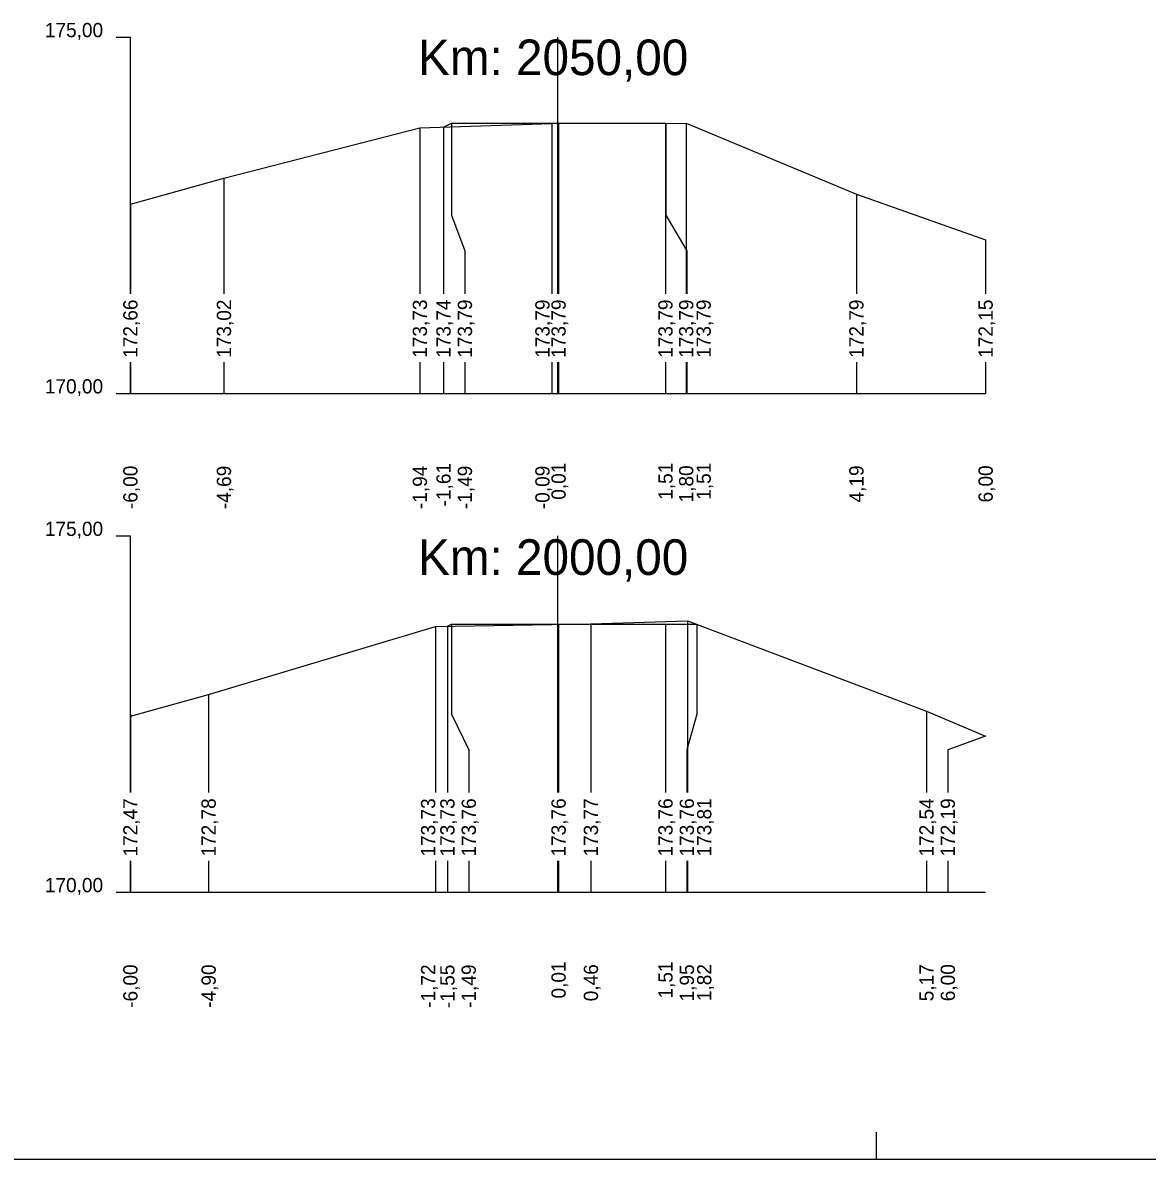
# Model space of a CAD drawing. Extents: x -614174 to -599765, y -1185887 to -1181080.
# Drawn here: x -600970.94 to -600955.16, y -1184449.09 to -1184433.14 of the extents above; entities that cross this region are included whole.
import ezdxf

# ---------------------------------------------------------------- set-up
doc = ezdxf.new("R2010")
doc.units = 0
for name, color, linetype in [('11', 7, 'Continuous'), ('16', 7, 'Continuous'), ('21', 7, 'Continuous'), ('28', 7, 'Continuous'), ('59', 7, 'Continuous'), ('8', 7, 'Continuous'), ('návrh', 7, 'Continuous')]:
    doc.layers.add(name, color=color, linetype=linetype)

msp = doc.modelspace()

# ---------------------------------------------------------------- linework, layer by layer
for points in [[(-600969.427, -1184435.687), (-600968.114, -1184435.322), (-600965.365, -1184434.616), (-600963.513, -1184434.554), (-600961.628, -1184434.549), (-600959.24, -1184435.547), (-600957.427, -1184436.188)], [(-600965.033, -1184434.605), (-600964.919, -1184434.548), (-600963.419, -1184434.548), (-600961.919, -1184434.548), (-600961.916, -1184434.55)], [(-600965.033, -1184434.605), (-600965.033, -1184434.605), (-600965.033, -1184434.605)], [(-600964.919, -1184434.548), (-600964.919, -1184434.548), (-600964.919, -1184434.548)], [(-600963.419, -1184434.548), (-600963.419, -1184434.548), (-600963.419, -1184434.548)], [(-600961.919, -1184434.548), (-600961.919, -1184434.548), (-600961.919, -1184434.548)], [(-600969.427, -1184442.871), (-600968.329, -1184442.565), (-600965.145, -1184441.613), (-600962.965, -1184441.576), (-600961.608, -1184441.531), (-600958.257, -1184442.802), (-600957.427, -1184443.151)], [(-600964.979, -1184441.61), (-600964.919, -1184441.58), (-600963.419, -1184441.58), (-600961.919, -1184441.58), (-600961.477, -1184441.58)], [(-600964.979, -1184441.61), (-600964.979, -1184441.61), (-600964.979, -1184441.61)], [(-600964.919, -1184441.58), (-600964.919, -1184441.58), (-600964.919, -1184441.58)], [(-600963.419, -1184441.58), (-600963.419, -1184441.58), (-600963.419, -1184441.58)], [(-600961.919, -1184441.58), (-600961.919, -1184441.58), (-600961.919, -1184441.58)]]:
    msp.add_lwpolyline(points)
at = {"layer": '11'}
for points in [[(-600965.365, -1184434.616), (-600965.365, -1184435.842), (-600965.365, -1184436.342), (-600965.365, -1184436.944)], [(-600965.033, -1184434.605), (-600965.033, -1184435.842), (-600965.033, -1184436.342), (-600965.033, -1184436.944)], [(-600964.919, -1184434.548), (-600964.919, -1184435.842), (-600964.733, -1184436.342), (-600964.733, -1184436.944)], [(-600963.513, -1184434.554), (-600963.513, -1184435.842), (-600963.513, -1184436.342), (-600963.513, -1184436.944)], [(-600963.419, -1184434.548), (-600963.419, -1184435.842), (-600963.419, -1184436.342), (-600963.419, -1184436.944)], [(-600961.919, -1184434.548), (-600961.919, -1184435.842), (-600961.919, -1184436.342), (-600961.919, -1184436.944)], [(-600961.916, -1184434.55), (-600961.916, -1184435.842), (-600961.619, -1184436.342), (-600961.619, -1184436.944)], [(-600961.628, -1184434.549), (-600961.628, -1184435.842), (-600961.628, -1184436.342), (-600961.628, -1184436.944)], [(-600968.114, -1184435.322), (-600968.114, -1184435.842), (-600968.114, -1184436.342), (-600968.114, -1184436.944)], [(-600959.24, -1184435.547), (-600959.24, -1184435.842), (-600959.24, -1184436.342), (-600959.24, -1184436.944)], [(-600969.427, -1184435.687), (-600969.427, -1184435.842), (-600969.427, -1184436.342), (-600969.427, -1184436.944)], [(-600957.427, -1184436.188), (-600957.427, -1184436.342), (-600957.427, -1184436.944)], [(-600969.427, -1184437.902), (-600969.427, -1184438.342)], [(-600968.114, -1184437.902), (-600968.114, -1184438.342)], [(-600965.365, -1184437.902), (-600965.365, -1184438.342)], [(-600965.033, -1184437.902), (-600965.033, -1184438.342)], [(-600964.733, -1184437.902), (-600964.733, -1184438.342)], [(-600963.513, -1184437.902), (-600963.513, -1184438.342)], [(-600963.419, -1184437.902), (-600963.419, -1184438.342)], [(-600961.919, -1184437.902), (-600961.919, -1184438.342)], [(-600961.628, -1184437.902), (-600961.628, -1184438.342)], [(-600961.619, -1184437.902), (-600961.619, -1184438.342)], [(-600959.24, -1184437.902), (-600959.24, -1184438.342)], [(-600957.427, -1184437.902), (-600957.427, -1184438.342)], [(-600961.608, -1184441.531), (-600961.608, -1184442.842), (-600961.608, -1184443.342), (-600961.608, -1184443.944)], [(-600965.145, -1184441.613), (-600965.145, -1184442.842), (-600965.145, -1184443.342), (-600965.145, -1184443.944)], [(-600964.979, -1184441.61), (-600964.979, -1184442.842), (-600964.979, -1184443.342), (-600964.979, -1184443.944)], [(-600964.919, -1184441.58), (-600964.919, -1184442.842), (-600964.679, -1184443.342), (-600964.679, -1184443.944)], [(-600963.419, -1184441.58), (-600963.419, -1184442.842), (-600963.419, -1184443.342), (-600963.419, -1184443.944)], [(-600962.965, -1184441.576), (-600962.965, -1184442.842), (-600962.965, -1184443.342), (-600962.965, -1184443.944)], [(-600961.919, -1184441.58), (-600961.919, -1184442.842), (-600961.919, -1184443.342), (-600961.919, -1184443.944)], [(-600961.477, -1184441.58), (-600961.477, -1184442.842), (-600961.619, -1184443.342), (-600961.619, -1184443.944)], [(-600968.329, -1184442.565), (-600968.329, -1184442.842), (-600968.329, -1184443.342), (-600968.329, -1184443.944)], [(-600958.257, -1184442.802), (-600958.257, -1184442.842), (-600958.257, -1184443.342), (-600958.257, -1184443.944)], [(-600969.427, -1184442.871), (-600969.427, -1184442.842), (-600969.427, -1184443.342), (-600969.427, -1184443.944)], [(-600957.427, -1184443.151), (-600957.957, -1184443.342), (-600957.957, -1184443.944)], [(-600969.427, -1184444.902), (-600969.427, -1184445.342)], [(-600968.329, -1184444.902), (-600968.329, -1184445.342)], [(-600965.145, -1184444.902), (-600965.145, -1184445.342)], [(-600964.979, -1184444.902), (-600964.979, -1184445.342)], [(-600964.679, -1184444.902), (-600964.679, -1184445.342)], [(-600963.419, -1184444.902), (-600963.419, -1184445.342)], [(-600962.965, -1184444.902), (-600962.965, -1184445.342)], [(-600961.919, -1184444.902), (-600961.919, -1184445.342)], [(-600961.619, -1184444.902), (-600961.619, -1184445.342)], [(-600961.608, -1184444.902), (-600961.608, -1184445.342)], [(-600958.257, -1184444.902), (-600958.257, -1184445.342)], [(-600957.957, -1184444.902), (-600957.957, -1184445.342)]]:
    msp.add_lwpolyline(points, dxfattribs=at)
at = {"layer": '16'}
for p, q in [((-600969.427, -1184438.342), (-600957.427, -1184438.342)), ((-600969.427, -1184445.342), (-600957.427, -1184445.342))]:
    msp.add_line(p, q, dxfattribs=at)
for points in [[(-600961.916, -1184434.55), (-600961.916, -1184434.55)], [(-600961.916, -1184434.55), (-600961.916, -1184434.55)], [(-600961.477, -1184441.58), (-600961.477, -1184441.58), (-600961.477, -1184441.58)]]:
    msp.add_lwpolyline(points, dxfattribs=at)
at = {"layer": '21'}
for p, q in [((-600969.627, -1184433.342), (-600969.427, -1184433.342)), ((-600969.627, -1184438.342), (-600969.427, -1184438.342)), ((-600969.627, -1184440.342), (-600969.427, -1184440.342)), ((-600969.627, -1184445.342), (-600969.427, -1184445.342))]:
    msp.add_line(p, q, dxfattribs=at)
at = {"layer": '28'}
for p, q in [((-600963.427, -1184436.944), (-600963.427, -1184433.342)), ((-600963.427, -1184438.342), (-600963.427, -1184437.902)), ((-600963.427, -1184443.944), (-600963.427, -1184440.342)), ((-600963.427, -1184445.342), (-600963.427, -1184444.902))]:
    msp.add_line(p, q, dxfattribs=at)
at = {"layer": '8'}
for p, q in [((-600969.427, -1184436.944), (-600969.427, -1184433.342)), ((-600969.427, -1184438.342), (-600969.427, -1184437.902)), ((-600969.427, -1184443.944), (-600969.427, -1184440.342)), ((-600969.427, -1184445.342), (-600969.427, -1184444.902))]:
    msp.add_line(p, q, dxfattribs=at)
at = {"layer": 'návrh'}
for p, q in [((-600958.957, -1184449.09), (-600958.957, -1184448.71)), ((-600979.957, -1184449.09), (-600958.957, -1184449.09)), ((-600958.957, -1184449.09), (-600937.957, -1184449.09))]:
    msp.add_line(p, q, dxfattribs=at)

# ---------------------------------------------------------------- texts
at = {"layer": '16'}
for s, p in [('172,66', (-600969.327, -1184437.842)), ('173,02', (-600968.014, -1184437.842)), ('173,73', (-600965.265, -1184437.842)), ('173,74', (-600964.933, -1184437.842)), ('173,79', (-600964.633, -1184437.842)), ('173,79', (-600963.545, -1184437.842)), ('173,79', (-600963.319, -1184437.842)), ('173,79', (-600961.819, -1184437.842)), ('173,79', (-600961.528, -1184437.842)), ('173,79', (-600961.283, -1184437.842)), ('172,79', (-600959.14, -1184437.842)), ('172,15', (-600957.327, -1184437.842)), ('172,47', (-600969.327, -1184444.842)), ('172,78', (-600968.229, -1184444.842)), ('173,73', (-600965.149, -1184444.842)), ('173,73', (-600964.879, -1184444.842)), ('173,76', (-600964.579, -1184444.842)), ('173,76', (-600963.319, -1184444.842)), ('173,77', (-600962.865, -1184444.842)), ('173,76', (-600961.819, -1184444.842)), ('173,76', (-600961.519, -1184444.842)), ('173,81', (-600961.275, -1184444.842)), ('172,54', (-600958.157, -1184444.842)), ('172,19', (-600957.857, -1184444.842))]:
    msp.add_text(s, height=0.2, rotation=90, dxfattribs=at).set_placement(p)
at = {"layer": '21'}
for s, p in [('175,00', (-600970.627, -1184433.342)), ('170,00', (-600970.627, -1184438.342)), ('175,00', (-600970.627, -1184440.342)), ('170,00', (-600970.627, -1184445.342))]:
    msp.add_text(s, height=0.2, dxfattribs=at).set_placement(p)
at = {"layer": '28'}
for s, p in [('Km: 2050,00', (-600965.39, -1184433.875)), ('Km: 2000,00', (-600965.39, -1184440.889))]:
    msp.add_text(s, height=0.5, dxfattribs=at).set_placement(p)
at = {"layer": '59'}
for s, p in [('-6,00', (-600969.327, -1184439.965)), ('-4,69', (-600968.014, -1184439.966)), ('-1,94', (-600965.265, -1184439.965)), ('-1,61', (-600964.933, -1184439.927)), ('-1,49', (-600964.633, -1184439.966)), ('-0,09', (-600963.545, -1184439.966)), ('0,01', (-600963.319, -1184439.834)), ('1,51', (-600961.819, -1184439.834)), ('1,80', (-600961.528, -1184439.872)), ('1,51', (-600961.283, -1184439.834)), ('4,19', (-600959.14, -1184439.873)), ('6,00', (-600957.327, -1184439.872)), ('0,01', (-600963.319, -1184446.834)), ('1,51', (-600961.819, -1184446.834)), ('-6,00', (-600969.327, -1184446.965)), ('-4,90', (-600968.229, -1184446.965)), ('-1,72', (-600965.149, -1184446.964)), ('-1,55', (-600964.879, -1184446.968)), ('-1,49', (-600964.579, -1184446.966)), ('0,46', (-600962.865, -1184446.873)), ('1,95', (-600961.519, -1184446.875)), ('1,82', (-600961.275, -1184446.871)), ('5,17', (-600958.157, -1184446.873)), ('6,00', (-600957.857, -1184446.872))]:
    msp.add_text(s, height=0.2, rotation=90, dxfattribs=at).set_placement(p)

doc.saveas('drawing.dxf')
